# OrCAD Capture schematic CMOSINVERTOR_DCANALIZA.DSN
size A
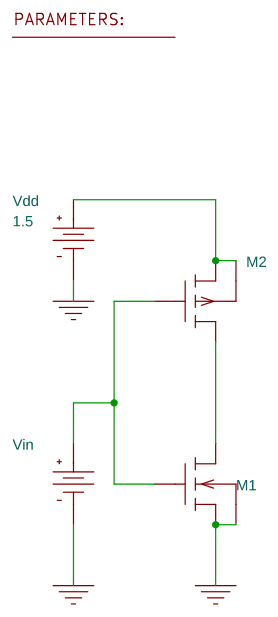
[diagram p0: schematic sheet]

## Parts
1  PARAM
M1  MbreakN
M2  MbreakP4
Vdd  VDC
Vin  VDC

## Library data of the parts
1 = PARAM: W1: 25u; W2: 75u
M1 = MbreakN: AD: {3*0.35u*W1}; AS: {3*0.35u*W1}; L: 0.35u; PD: {W1+6*0.35u}; PS: {W1+6*0.35u}; W: {W1}
M2 = MbreakP4: AD: {3*0.35u*W2}; AS: {3*0.35u*W2}; L: 0.35u; PD: {W2+6*0.35u}; PS: {W2+6*0.35u}; W: {W2}
Vdd = VDC: DC: 1.5
Vin = VDC

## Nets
0: M1.0(s) M1.4(b) Vdd.1(-) Vin.1(-)
N00319: M1.2(d) M2.2(d)
N00354: M2.1(s) M2.4(b) Vdd.0(+)
N00392: M1.1(g) M2.0(g) Vin.0(+)
